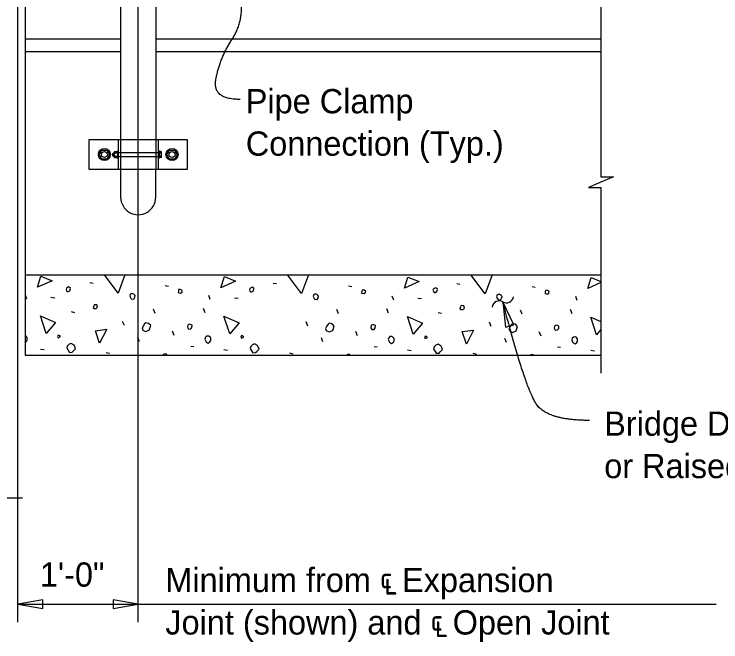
# Model space of a CAD drawing. Extents: x 0 to 41, y -96 to 25.
# Drawn here: x 24.29 to 30.16, y 9.59 to 14.8 of the extents above; entities that cross this region are included whole.
import ezdxf

# ---------------------------------------------------------------- set-up
doc = ezdxf.new("R2010")
doc.units = 0
for name, color, linetype in [('CL_Major', 7, 'Continuous'), ('Dimension', 7, 'Continuous'), ('Miscellaneous', 7, 'Continuous'), ('SteelMisc', 7, 'Continuous'), ('SteelMisc_h', 7, 'Continuous'), ('SupstrConc', 7, 'Continuous'), ('TextStructures', 7, 'Continuous')]:
    doc.layers.add(name, color=color, linetype=linetype)

msp = doc.modelspace()

# ---------------------------------------------------------------- linework, layer by layer
at = {"layer": 'CL_Major'}
for p, q in [((25.3238, 9.7541), (25.3238, 24.2317)), ((24.3238, 9.7541), (24.3238, 15.6384))]:
    msp.add_line(p, q, dxfattribs=at)
at = {"layer": 'Dimension'}
msp.add_line((24.3238, 9.9041), (30.124, 9.9041), dxfattribs=at)
for points in [[(29.1682, 15.3052), (29.1682, 13.4544), (29.2716, 13.4544), (29.1682, 13.4094), (29.0649, 13.3644), (29.1682, 13.3644), (29.1682, 11.8219)], [(24.3634, 10.7839), (23.6664, 10.7839), (23.6664, 10.6676), (23.567, 10.8926), (23.567, 10.7839), (22.9118, 10.7839)]]:
    msp.add_lwpolyline(points, dxfattribs=at)
for points in [[(28.3531, 12.4148), (28.3753, 12.2047), (28.4433, 12.2238)], [(24.3238, 9.9041), (24.5321, 9.8688), (24.5321, 9.9394)], [(25.3238, 9.9042), (25.1156, 9.9395), (25.1156, 9.8689)]]:
    msp.add_lwpolyline(points, close=True, dxfattribs=at)
for centre, start, end in [((28.3823, 12.466), 239.84335, 351.57057), ((28.3224, 12.3629), 59.84335, 171.57057)]:
    msp.add_arc(centre, 0.0596, start, end, dxfattribs=at)
for points in [[(26.1714, 14.0966), (25.9344, 14.0943), (26.0058, 14.4456), (26.2043, 14.7506), (26.1489, 15.1434), (25.7297, 15.1203)], [(29.0716, 11.4303), (28.7312, 11.4303), (28.5421, 11.6859), (28.353, 12.4147)]]:
    msp.add_open_spline(points, degree=2, dxfattribs=at)
at = {"layer": 'Miscellaneous'}
for p, q in [((25.1162, 13.6316), (25.1162, 13.6437)), ((25.1219, 13.6316), (25.1219, 13.6437)), ((24.9224, 12.5748), (24.9489, 12.5695)), ((26.4462, 12.5713), (26.4727, 12.566)), ((27.97, 12.5678), (27.9966, 12.5625)), ((25.5482, 12.5501), (25.5747, 12.5448)), ((27.072, 12.5466), (27.0985, 12.5413)), ((28.5958, 12.543), (28.6223, 12.5377)), ((24.3992, 12.437), (24.3868, 12.4705)), ((24.5989, 12.4529), (24.6307, 12.4493)), ((25.923, 12.4334), (25.9106, 12.467)), ((26.1227, 12.4493), (26.1545, 12.4458)), ((27.4468, 12.4299), (27.4344, 12.4635)), ((28.9706, 12.4264), (28.9582, 12.4599)), ((27.6465, 12.4458), (27.6784, 12.4423)), ((24.7668, 12.3344), (24.7951, 12.3274)), ((25.4651, 12.3185), (25.451, 12.3539)), ((25.8805, 12.3238), (25.8664, 12.3592)), ((26.9889, 12.315), (26.9748, 12.3503)), ((27.4044, 12.3203), (27.3902, 12.3556)), ((28.5127, 12.3114), (28.4986, 12.3468)), ((28.9282, 12.3167), (28.914, 12.3521)), ((27.8145, 12.3274), (27.8428, 12.3203)), ((25.2088, 12.2178), (25.1946, 12.2531)), ((26.7326, 12.2142), (26.7185, 12.2496)), ((28.2564, 12.2107), (28.2423, 12.246)), ((25.6224, 12.1364), (25.6083, 12.1718)), ((27.1463, 12.1329), (27.1321, 12.1683)), ((28.6701, 12.1294), (28.6559, 12.1647)), ((25.3343, 12.0852), (25.3219, 12.1188)), ((26.8581, 12.0816), (26.8457, 12.1152)), ((28.3819, 12.0781), (28.3696, 12.1117)), ((25.7603, 12.048), (25.7851, 12.0445)), ((27.2841, 12.0445), (27.3089, 12.041)), ((28.808, 12.041), (28.8327, 12.0374)), ((24.5123, 12.0233), (24.5423, 12.018)), ((25.0568, 11.995), (25.085, 11.9879)), ((26.0361, 12.0198), (26.0662, 12.0145)), ((26.5806, 11.9915), (26.6089, 11.9844)), ((27.5599, 12.0162), (27.59, 12.0109)), ((28.1044, 11.9879), (28.1327, 11.9809)), ((29.0837, 12.0127), (29.1138, 12.0074))]:
    msp.add_line(p, q, dxfattribs=at)
for points in [[(24.4875, 12.536), (24.5158, 12.6279), (24.6095, 12.5908), (24.4875, 12.536)], [(25.1575, 12.4882), (25.0433, 12.6385)], [(25.2137, 12.6385), (25.1575, 12.4882)], [(26.0114, 12.5324), (26.0396, 12.6243), (26.1333, 12.5872), (26.0114, 12.5324)], [(26.6813, 12.4847), (26.5645, 12.6385)], [(26.7388, 12.6385), (26.6813, 12.4847)], [(28.2052, 12.4812), (28.0856, 12.6385)], [(28.264, 12.6385), (28.2052, 12.4812)], [(27.5352, 12.5289), (27.5635, 12.6208), (27.6571, 12.5837), (27.5352, 12.5289)], [(29.059, 12.5253), (29.0873, 12.6173), (29.1682, 12.5852)], [(29.1682, 12.5744), (29.059, 12.5253)], [(24.735, 12.5006), (24.7421, 12.5006), (24.7562, 12.5077), (24.7615, 12.5236), (24.7598, 12.5324), (24.7456, 12.5395), (24.728, 12.5289), (24.7244, 12.5183), (24.728, 12.5077), (24.735, 12.5006)], [(25.656, 12.4918), (25.6755, 12.4865), (25.6879, 12.4953), (25.6896, 12.5077), (25.6861, 12.5112), (25.6719, 12.5183), (25.6596, 12.5165), (25.6578, 12.5041), (25.656, 12.4918)], [(26.2588, 12.4971), (26.2659, 12.4971), (26.2801, 12.5041), (26.2854, 12.52), (26.2836, 12.5289), (26.2694, 12.536), (26.2518, 12.5253), (26.2482, 12.5147), (26.2518, 12.5041), (26.2588, 12.4971)], [(27.1798, 12.4882), (27.1993, 12.4829), (27.2117, 12.4918), (27.2134, 12.5041), (27.2099, 12.5077), (27.1958, 12.5147), (27.1834, 12.513), (27.1816, 12.5006), (27.1798, 12.4882)], [(27.7827, 12.4935), (27.7897, 12.4935), (27.8039, 12.5006), (27.8092, 12.5165), (27.8074, 12.5253), (27.7933, 12.5324), (27.7756, 12.5218), (27.7721, 12.5112), (27.7756, 12.5006), (27.7827, 12.4935)], [(28.7037, 12.4847), (28.7231, 12.4794), (28.7355, 12.4882), (28.7373, 12.5006), (28.7337, 12.5041), (28.7196, 12.5112), (28.7072, 12.5094), (28.7054, 12.4971), (28.7037, 12.4847)], [(25.2565, 12.4564), (25.2654, 12.4405), (25.2866, 12.437), (25.2954, 12.4529), (25.2989, 12.467), (25.2901, 12.4758), (25.2742, 12.4847), (25.2583, 12.4794), (25.253, 12.4635), (25.2565, 12.4564)], [(26.7803, 12.4529), (26.7892, 12.437), (26.8104, 12.4334), (26.8192, 12.4493), (26.8228, 12.4635), (26.8139, 12.4723), (26.798, 12.4812), (26.7821, 12.4758), (26.7768, 12.4599), (26.7803, 12.4529)], [(28.3041, 12.4493), (28.313, 12.4334), (28.3342, 12.4299), (28.343, 12.4458), (28.3466, 12.4599), (28.3377, 12.4688), (28.3218, 12.4776), (28.3059, 12.4723), (28.3006, 12.4564), (28.3041, 12.4493)], [(24.9542, 12.3592), (24.9754, 12.3592), (24.9861, 12.3698), (24.9807, 12.3892), (24.9578, 12.391), (24.9542, 12.3804), (24.9489, 12.3715), (24.9542, 12.3592), (24.9507, 12.3627)], [(28.0019, 12.3521), (28.0231, 12.3521), (28.0337, 12.3627), (28.0284, 12.3822), (28.0054, 12.3839), (28.0019, 12.3733), (27.9966, 12.3645), (28.0019, 12.3521), (27.9983, 12.3556)], [(24.56, 12.1523), (24.5123, 12.2991), (24.6378, 12.2443), (24.56, 12.1523)], [(26.0838, 12.1488), (26.0361, 12.2955), (26.1616, 12.2407), (26.0838, 12.1488)], [(27.6076, 12.1453), (27.5599, 12.292), (27.6854, 12.2372), (27.6076, 12.1453)], [(29.1315, 12.1417), (29.0837, 12.2885), (29.1682, 12.2516)], [(25.3626, 12.1806), (25.3856, 12.1683), (25.4156, 12.1806), (25.428, 12.2178), (25.4103, 12.2354), (25.3873, 12.2407), (25.3767, 12.2337), (25.3644, 12.2142), (25.3555, 12.1983), (25.3626, 12.1806)], [(25.732, 12.2036), (25.7409, 12.1877), (25.7603, 12.1895), (25.7692, 12.2018), (25.7709, 12.2213), (25.7586, 12.2266), (25.7497, 12.2284), (25.7391, 12.2248), (25.7356, 12.2213), (25.732, 12.2036)], [(26.8864, 12.1771), (26.9094, 12.1647), (26.9394, 12.1771), (26.9518, 12.2142), (26.9341, 12.2319), (26.9111, 12.2372), (26.9005, 12.2301), (26.8882, 12.2107), (26.8793, 12.1948), (26.8864, 12.1771)], [(27.2559, 12.2001), (27.2647, 12.1842), (27.2841, 12.1859), (27.293, 12.1983), (27.2948, 12.2178), (27.2824, 12.2231), (27.2735, 12.2248), (27.2629, 12.2213), (27.2594, 12.2178), (27.2559, 12.2001)], [(28.4102, 12.1736), (28.4332, 12.1612), (28.4632, 12.1736), (28.4756, 12.2107), (28.4579, 12.2284), (28.435, 12.2337), (28.4244, 12.2266), (28.412, 12.2071), (28.4031, 12.1912), (28.4102, 12.1736)], [(28.7797, 12.1965), (28.7885, 12.1806), (28.808, 12.1824), (28.8168, 12.1948), (28.8186, 12.2142), (28.8062, 12.2195), (28.7974, 12.2213), (28.7867, 12.2178), (28.7832, 12.2142), (28.7797, 12.1965)], [(25.002, 12.071), (24.9684, 12.1753), (25.0621, 12.1877), (25.002, 12.071)], [(28.0496, 12.064), (28.016, 12.1683), (28.1097, 12.1806), (28.0496, 12.064)], [(29.1682, 12.1852), (29.1315, 12.1417)], [(24.385, 12.079), (24.3956, 12.0869), (24.4027, 12.0975), (24.4027, 12.1188), (24.3868, 12.1347), (24.385, 12.1345)], [(24.659, 12.117), (24.6785, 12.1258), (24.6714, 12.1329), (24.659, 12.1382), (24.6537, 12.1258), (24.659, 12.117)], [(25.877, 12.1046), (25.8876, 12.0834), (25.9053, 12.0728), (25.9194, 12.0834), (25.9265, 12.094), (25.9265, 12.1152), (25.9106, 12.1311), (25.8911, 12.1294), (25.8823, 12.1205), (25.877, 12.1046)], [(26.1828, 12.1135), (26.2023, 12.1223), (26.1952, 12.1294), (26.1828, 12.1347), (26.1775, 12.1223), (26.1828, 12.1135)], [(27.4008, 12.1011), (27.4114, 12.0799), (27.4291, 12.0693), (27.4432, 12.0799), (27.4503, 12.0905), (27.4503, 12.1117), (27.4344, 12.1276), (27.415, 12.1258), (27.4061, 12.117), (27.4008, 12.1011)], [(27.7066, 12.1099), (27.7261, 12.1188), (27.719, 12.1258), (27.7066, 12.1311), (27.7013, 12.1188), (27.7066, 12.1099)], [(28.9246, 12.0975), (28.9352, 12.0763), (28.9529, 12.0657), (28.9671, 12.0763), (28.9741, 12.0869), (28.9741, 12.1082), (28.9582, 12.1241), (28.9388, 12.1223), (28.9299, 12.1135), (28.9246, 12.0975)], [(24.7297, 12.0321), (24.7527, 11.995), (24.7757, 11.9968), (24.7845, 12.0056), (24.804, 12.0251), (24.7916, 12.0551), (24.7668, 12.0693), (24.7492, 12.0622), (24.735, 12.048), (24.7297, 12.0321)], [(26.2535, 12.0286), (26.2765, 11.9915), (26.2995, 11.9932), (26.3083, 12.0021), (26.3278, 12.0215), (26.3154, 12.0516), (26.2907, 12.0657), (26.273, 12.0587), (26.2588, 12.0445), (26.2535, 12.0286)], [(27.7774, 12.0251), (27.8003, 11.9879), (27.8233, 11.9897), (27.8322, 11.9986), (27.8516, 12.018), (27.8392, 12.048), (27.8145, 12.0622), (27.7968, 12.0551), (27.7827, 12.041), (27.7774, 12.0251)], [(25.5606, 11.9718), (25.5588, 11.9809), (25.55, 11.9826), (25.5376, 11.9809), (25.5285, 11.9718)], [(27.0837, 11.9718), (27.0826, 11.9773), (27.0738, 11.9791), (27.0614, 11.9773), (27.0559, 11.9718)], [(28.6068, 11.9718), (28.6064, 11.9738), (28.5976, 11.9756), (28.5852, 11.9738), (28.5832, 11.9718)]]:
    msp.add_lwpolyline(points, dxfattribs=at)
at = {"layer": 'SteelMisc'}
for p, q in [((25.1779, 15.0135), (25.1779, 13.7635)), ((25.4696, 15.0135), (25.4696, 13.7635)), ((24.9178, 13.7635), (25.7297, 13.7635)), ((24.9178, 13.5135), (24.9178, 13.7635)), ((25.1571, 13.7635), (25.1571, 13.5135)), ((25.4904, 13.7635), (25.4904, 13.5135)), ((25.7297, 13.7635), (25.7297, 13.5135)), ((25.1134, 13.6465), (25.119, 13.6531)), ((25.1134, 13.6288), (25.1134, 13.6465)), ((25.1134, 13.6288), (25.119, 13.6232)), ((25.119, 13.6531), (25.1255, 13.6531)), ((25.119, 13.6232), (25.119, 13.6531)), ((25.119, 13.6232), (25.1255, 13.6232)), ((25.1255, 13.6564), (25.1255, 13.6207)), ((25.1302, 13.6515), (25.1505, 13.6515)), ((25.1302, 13.6256), (25.1505, 13.6256)), ((25.1304, 13.6646), (25.1505, 13.6646)), ((25.1505, 13.6688), (25.1505, 13.6082)), ((25.1505, 13.6688), (25.1571, 13.6688)), ((25.1505, 13.6646), (25.1505, 13.6126)), ((25.4967, 13.6688), (25.4906, 13.6688)), ((25.4967, 13.6688), (25.4967, 13.6082)), ((25.5114, 13.6645), (25.4967, 13.6645)), ((25.5115, 13.6515), (25.4967, 13.6515)), ((25.5115, 13.6255), (25.4967, 13.6255)), ((25.5165, 13.6191), (25.5165, 13.658)), ((25.1305, 13.6126), (25.1505, 13.6126)), ((25.1505, 13.6082), (25.1571, 13.6082)), ((25.4967, 13.6082), (25.4906, 13.6082)), ((25.5114, 13.6125), (25.4967, 13.6125)), ((25.7297, 13.5135), (24.9178, 13.5135)), ((25.1779, 13.5135), (25.1779, 13.2844)), ((25.4696, 13.2844), (25.4696, 13.5135))]:
    msp.add_line(p, q, dxfattribs=at)
for points in [[(25.0211, 13.6761), (25.0644, 13.6761), (25.0861, 13.6385), (25.0644, 13.601), (25.0211, 13.601), (24.9994, 13.6385)], [(25.5831, 13.6761), (25.6264, 13.6761), (25.6481, 13.6385), (25.6264, 13.601), (25.5831, 13.601), (25.5614, 13.6385)]]:
    msp.add_lwpolyline(points, close=True, dxfattribs=at)
for centre, radius in [((25.0428, 13.6385), 0.05), ((25.6047, 13.6385), 0.05), ((25.0428, 13.6385), 0.025), ((25.6047, 13.6385), 0.025)]:
    msp.add_circle(centre, radius, dxfattribs=at)
for centre, radius, start, end in [((25.1321, 13.658), 0.00674, 104.48908, 254.18889), ((25.145, 13.6385), 0.0196, 138.62797, 221.37203), ((25.1321, 13.6191), 0.00673, 105.7823, 255.54039), ((25.5097, 13.658), 0.00673, 285.7823, 75.54039), ((25.5097, 13.6191), 0.00674, 284.48908, 74.18889), ((25.4968, 13.6385), 0.0196, 318.62797, 41.37203)]:
    msp.add_arc(centre, radius, start, end, dxfattribs=at)
msp.add_ellipse((25.3238, 13.2844), major_axis=(0, 0.1458), ratio=0.999499, start_param=1.570796, end_param=4.712389, dxfattribs=at)
at = {"layer": 'SteelMisc_h'}
for p, q in [((25.1779, 13.7635), (25.1779, 13.5135)), ((25.4696, 13.7635), (25.4696, 13.5135)), ((25.4904, 13.6531), (25.1255, 13.6531)), ((25.1255, 13.6232), (25.4904, 13.6232))]:
    msp.add_line(p, q, dxfattribs=at)
at = {"layer": 'SupstrConc'}
for p, q in [((24.385, 15.6384), (24.385, 11.9718)), ((24.385, 14.5986), (25.1779, 14.5986)), ((25.4696, 14.5986), (29.1682, 14.5986)), ((25.4696, 14.5986), (26.7107, 14.5986)), ((24.385, 14.4945), (25.1779, 14.4945)), ((25.4696, 14.4945), (29.1682, 14.4945)), ((25.4696, 14.4945), (26.7107, 14.4945)), ((24.385, 12.6385), (29.1682, 12.6385)), ((24.385, 11.9718), (29.1682, 11.9718))]:
    msp.add_line(p, q, dxfattribs=at)

# ---------------------------------------------------------------- texts
at = {"layer": 'Dimension'}
for s, p in [('Pipe Clamp ', (26.2174, 13.9807)), ('Connection (Typ.)', (26.2174, 13.6287)), ('Bridge Deck (shown)', (29.1951, 11.3026)), ('or Raised Sidewalk', (29.1951, 10.9506)), ('Minimum from ℄ Expansion', (25.5492, 10.0037)), ('Joint (shown) and ℄ Open Joint ', (25.5492, 9.6517))]:
    msp.add_text(s, height=0.2016, dxfattribs=at).set_placement(p)
at = {"layer": 'TextStructures'}
msp.add_text('1\'-0"', height=0.2016, dxfattribs=at).set_placement((24.5069, 10.0491))

doc.saveas('drawing.dxf')
